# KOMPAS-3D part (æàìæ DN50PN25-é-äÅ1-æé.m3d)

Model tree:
1. Объединить компоненты:1  (labels: СЕНС DN50PN25-В-ДП1)
2. Эскиз:1
3. Операция выдавливания:1
     Расстояние 1 = 14
4. Фаска:1
     Угол = 45; Длина 1 = 2; Длина 2 = 2

Referenced files in D:\Савин\!СЕНСОР\3D для заказчика\!Новый перечень\СЕНС\5. СЕНС-В-ДП\DN50\: СЕНС DN50PN25-В-ДП1.a3d
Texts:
  СЕНС DN50PN25-В-ДП1-СВ
  ООО НПП Сенсор
  СЕНС DN50PN25-В-ДП1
